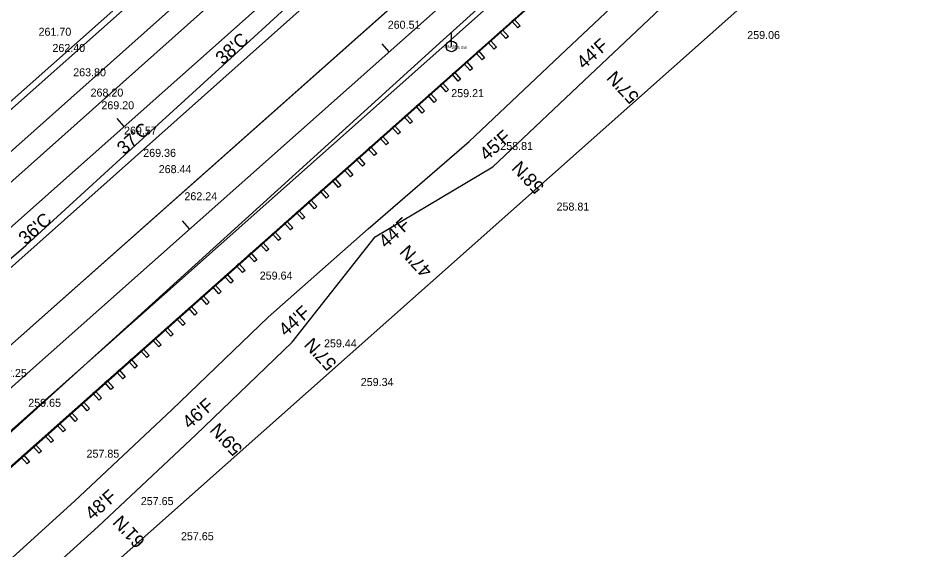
# Model space of a CAD drawing. Extents: x 49683 to 58852, y 49525 to 54803.
# Drawn here: x 54598 to 54939.2, y 52384.9 to 52584.3 of the extents above; entities that cross this region are included whole.
import ezdxf

# ---------------------------------------------------------------- set-up
doc = ezdxf.new("R2010")
doc.units = 0
for name, color, linetype in [('Level 1', 7, 'Continuous'), ('Level 11', 7, 'Continuous'), ('Level 13', 7, 'Continuous'), ('Level 18', 7, 'Continuous'), ('Level 19', 7, 'Continuous'), ('Level 20', 7, 'Continuous'), ('Level 27', 7, 'Continuous'), ('Level 3', 7, 'Continuous'), ('Level 32', 7, 'Continuous'), ('Level 33', 7, 'Continuous'), ('Level 48', 7, 'Continuous'), ('Level 59', 7, 'Continuous'), ('Level 61', 7, 'Continuous'), ('Level 8', 7, 'Continuous'), ('Level 9', 7, 'Continuous')]:
    doc.layers.add(name, color=color, linetype=linetype)

# ---------------------------------------------------------------- blocks, each defined once
blk = doc.blocks.new('GW')
at = {"layer": 'Level 9'}
blk.add_line((0, 0), (0, 5), dxfattribs=at)
blk.add_circle((0, 0), 2, dxfattribs=at)

msp = doc.modelspace()

# ---------------------------------------------------------------- linework, layer by layer
at = {"layer": 'Level 1'}
for p, q in [((52544.81, 50683.3), (55534.58, 53340.86)), ((54637.69, 52543.63), (54635.03, 52546.62))]:
    msp.add_line(p, q, dxfattribs=at)
at = {"layer": 'Level 11'}
for p, q in [((54757.25, 52576.08), (54913.43, 52717.81)), ((54324.2, 52292.62), (54711.21, 52637.72)), ((54450.3, 52297.6), (54757.25, 52576.08))]:
    msp.add_line(p, q, dxfattribs=at)
at = {"layer": 'Level 13'}
for p, q in [((55279.53, 53070), (53969.03, 51905.11)), ((54971.79, 52884.76), (53925.18, 51954.44))]:
    msp.add_line(p, q, dxfattribs=at)
at = {"layer": 'Level 18'}
for p, q in [((54803.29, 52572.34), (54839.6, 52606.76)), ((54674.65, 52566.54), (54711.55, 52600.29)), ((54812.22, 52562.88), (54848.51, 52597.3)), ((54766.92, 52538), (54803.29, 52572.34)), ((54637.73, 52532.81), (54674.65, 52566.54)), ((54775.84, 52528.54), (54812.22, 52562.88)), ((54729.15, 52505.23), (54766.92, 52538)), ((54600.86, 52499.03), (54637.73, 52532.81)), ((54731.79, 52502.23), (54775.84, 52528.54)), ((54691.65, 52472.16), (54729.15, 52505.23)), ((54700.66, 52462.79), (54731.79, 52502.23)), ((54562.88, 52466.5), (54600.86, 52499.03)), ((54655.59, 52437.46), (54691.65, 52472.16)), ((54664.55, 52428.04), (54700.66, 52462.79)), ((54619.13, 52403.22), (54655.59, 52437.46)), ((54627.94, 52393.65), (54664.55, 52428.04)), ((54582.03, 52369.7), (54619.13, 52403.22)), ((54590.74, 52360.05), (54627.94, 52393.65))]:
    msp.add_line(p, q, dxfattribs=at)
at = {"layer": 'Level 19'}
for p, q in [((54181.77, 52078.16), (56150.85, 53828.45)), ((54736.98, 52571.68), (54734.32, 52574.67)), ((54662.24, 52505.24), (54659.58, 52508.23))]:
    msp.add_line(p, q, dxfattribs=at)
at = {"layer": 'Level 20'}
for p, q in [((54173.8, 52087.13), (55269.45, 53061.04)), ((54189.74, 52069.19), (55278.86, 53037.3))]:
    msp.add_line(p, q, dxfattribs=at)
at = {"layer": 'Level 27'}
for p, q in [((54196.38, 52061.72), (54970.77, 52750.06)), ((54196.55, 52061.53), (54970.94, 52749.87)), ((54782.99, 52583.14), (54783.87, 52583.92)), ((54783.87, 52583.92), (54786.13, 52581.38)), ((54785.25, 52580.6), (54782.99, 52583.14)), ((54786.13, 52581.38), (54785.25, 52580.6)), ((54778.5, 52579.15), (54779.39, 52579.94)), ((54780.76, 52576.61), (54778.5, 52579.15)), ((54779.39, 52579.94), (54781.64, 52577.4)), ((54781.64, 52577.4), (54780.76, 52576.61)), ((54774.02, 52575.17), (54774.9, 52575.95)), ((54776.28, 52572.63), (54774.02, 52575.17)), ((54774.9, 52575.95), (54777.16, 52573.41)), ((54769.53, 52571.18), (54770.42, 52571.97)), ((54771.79, 52568.64), (54769.53, 52571.18)), ((54770.42, 52571.97), (54772.68, 52569.42)), ((54777.16, 52573.41), (54776.28, 52572.63)), ((54765.05, 52567.19), (54765.93, 52567.98)), ((54767.31, 52564.65), (54765.05, 52567.19)), ((54765.93, 52567.98), (54768.19, 52565.44)), ((54772.68, 52569.42), (54771.79, 52568.64)), ((54760.56, 52563.21), (54761.45, 52563.99)), ((54761.45, 52563.99), (54763.71, 52561.45)), ((54768.19, 52565.44), (54767.31, 52564.65)), ((54756.08, 52559.22), (54756.96, 52560.01)), ((54756.96, 52560.01), (54759.22, 52557.47)), ((54762.82, 52560.67), (54760.56, 52563.21)), ((54763.71, 52561.45), (54762.82, 52560.67)), ((54758.34, 52556.68), (54756.08, 52559.22)), ((54759.22, 52557.47), (54758.34, 52556.68)), ((54751.6, 52555.24), (54752.48, 52556.02)), ((54753.85, 52552.69), (54751.6, 52555.24)), ((54752.48, 52556.02), (54754.74, 52553.48)), ((54754.74, 52553.48), (54753.85, 52552.69)), ((54747.11, 52551.25), (54747.99, 52552.03)), ((54749.37, 52548.71), (54747.11, 52551.25)), ((54747.99, 52552.03), (54750.25, 52549.49)), ((54742.63, 52547.26), (54743.51, 52548.05)), ((54744.89, 52544.72), (54742.63, 52547.26)), ((54743.51, 52548.05), (54745.77, 52545.51)), ((54750.25, 52549.49), (54749.37, 52548.71)), ((54738.14, 52543.28), (54739.03, 52544.06)), ((54740.4, 52540.74), (54738.14, 52543.28)), ((54739.03, 52544.06), (54741.28, 52541.52)), ((54745.77, 52545.51), (54744.89, 52544.72)), ((54733.66, 52539.29), (54734.54, 52540.08)), ((54734.54, 52540.08), (54736.8, 52537.53)), ((54741.28, 52541.52), (54740.4, 52540.74)), ((54729.17, 52535.3), (54730.06, 52536.09)), ((54730.06, 52536.09), (54732.32, 52533.55)), ((54735.92, 52536.75), (54733.66, 52539.29)), ((54736.8, 52537.53), (54735.92, 52536.75)), ((54731.43, 52532.76), (54729.17, 52535.3)), ((54732.32, 52533.55), (54731.43, 52532.76)), ((54724.69, 52531.32), (54725.57, 52532.1)), ((54726.95, 52528.78), (54724.69, 52531.32)), ((54725.57, 52532.1), (54727.83, 52529.56)), ((54727.83, 52529.56), (54726.95, 52528.78)), ((54720.2, 52527.33), (54721.09, 52528.12)), ((54722.46, 52524.79), (54720.2, 52527.33)), ((54721.09, 52528.12), (54723.35, 52525.58)), ((54715.72, 52523.35), (54716.6, 52524.13)), ((54717.98, 52520.8), (54715.72, 52523.35)), ((54716.6, 52524.13), (54718.86, 52521.59)), ((54723.35, 52525.58), (54722.46, 52524.79)), ((54711.24, 52519.36), (54712.12, 52520.15)), ((54713.49, 52516.82), (54711.24, 52519.36)), ((54712.12, 52520.15), (54714.38, 52517.6)), ((54718.86, 52521.59), (54717.98, 52520.8)), ((54706.75, 52515.37), (54707.63, 52516.16)), ((54707.63, 52516.16), (54709.89, 52513.62)), ((54714.38, 52517.6), (54713.49, 52516.82)), ((54702.27, 52511.39), (54703.15, 52512.17)), ((54703.15, 52512.17), (54705.41, 52509.63)), ((54709.01, 52512.83), (54706.75, 52515.37)), ((54709.89, 52513.62), (54709.01, 52512.83)), ((54704.53, 52508.85), (54702.27, 52511.39)), ((54705.41, 52509.63), (54704.53, 52508.85)), ((54697.78, 52507.4), (54698.67, 52508.19)), ((54700.04, 52504.86), (54697.78, 52507.4)), ((54698.67, 52508.19), (54700.92, 52505.65)), ((54700.92, 52505.65), (54700.04, 52504.86)), ((54693.3, 52503.42), (54694.18, 52504.2)), ((54695.56, 52500.87), (54693.3, 52503.42)), ((54694.18, 52504.2), (54696.44, 52501.66)), ((54688.81, 52499.43), (54689.7, 52500.21)), ((54691.07, 52496.89), (54688.81, 52499.43)), ((54689.7, 52500.21), (54691.96, 52497.67)), ((54696.44, 52501.66), (54695.56, 52500.87)), ((54684.33, 52495.44), (54685.21, 52496.23)), ((54686.59, 52492.9), (54684.33, 52495.44)), ((54685.21, 52496.23), (54687.47, 52493.69)), ((54691.96, 52497.67), (54691.07, 52496.89)), ((54679.84, 52491.46), (54680.73, 52492.24)), ((54680.73, 52492.24), (54682.99, 52489.7)), ((54687.47, 52493.69), (54686.59, 52492.9)), ((54675.36, 52487.47), (54676.24, 52488.26)), ((54676.24, 52488.26), (54678.5, 52485.71)), ((54682.1, 52488.92), (54679.84, 52491.46)), ((54682.99, 52489.7), (54682.1, 52488.92)), ((54677.62, 52484.93), (54675.36, 52487.47)), ((54678.5, 52485.71), (54677.62, 52484.93)), ((54670.88, 52483.48), (54671.76, 52484.27)), ((54673.13, 52480.94), (54670.88, 52483.48)), ((54671.76, 52484.27), (54674.02, 52481.73)), ((54674.02, 52481.73), (54673.13, 52480.94)), ((54666.39, 52479.5), (54667.27, 52480.28)), ((54668.65, 52476.96), (54666.39, 52479.5)), ((54667.27, 52480.28), (54669.53, 52477.74)), ((54661.91, 52475.51), (54662.79, 52476.3)), ((54664.16, 52472.97), (54661.91, 52475.51)), ((54662.79, 52476.3), (54665.05, 52473.76)), ((54669.53, 52477.74), (54668.65, 52476.96)), ((54657.42, 52471.53), (54658.31, 52472.31)), ((54659.68, 52468.98), (54657.42, 52471.53)), ((54658.31, 52472.31), (54660.56, 52469.77)), ((54665.05, 52473.76), (54664.16, 52472.97)), ((54652.94, 52467.54), (54653.82, 52468.33)), ((54653.82, 52468.33), (54656.08, 52465.78)), ((54660.56, 52469.77), (54659.68, 52468.98)), ((54655.2, 52465), (54652.94, 52467.54)), ((54656.08, 52465.78), (54655.2, 52465)), ((54648.45, 52463.55), (54649.34, 52464.34)), ((54650.71, 52461.01), (54648.45, 52463.55)), ((54649.34, 52464.34), (54651.6, 52461.8)), ((54651.6, 52461.8), (54650.71, 52461.01)), ((54643.97, 52459.57), (54644.85, 52460.35)), ((54646.23, 52457.03), (54643.97, 52459.57)), ((54644.85, 52460.35), (54647.11, 52457.81)), ((54647.11, 52457.81), (54646.23, 52457.03)), ((54639.48, 52455.58), (54640.37, 52456.37)), ((54641.74, 52453.04), (54639.48, 52455.58)), ((54640.37, 52456.37), (54642.63, 52453.83)), ((54635, 52451.6), (54635.88, 52452.38)), ((54637.26, 52449.05), (54635, 52451.6)), ((54635.88, 52452.38), (54638.14, 52449.84)), ((54642.63, 52453.83), (54641.74, 52453.04)), ((54630.52, 52447.61), (54631.4, 52448.39)), ((54632.77, 52445.07), (54630.52, 52447.61)), ((54631.4, 52448.39), (54633.66, 52445.85)), ((54638.14, 52449.84), (54637.26, 52449.05)), ((54626.03, 52443.62), (54626.91, 52444.41)), ((54626.91, 52444.41), (54629.17, 52441.87)), ((54633.66, 52445.85), (54632.77, 52445.07)), ((54628.29, 52441.08), (54626.03, 52443.62)), ((54629.17, 52441.87), (54628.29, 52441.08)), ((54621.55, 52439.64), (54622.43, 52440.42)), ((54623.8, 52437.1), (54621.55, 52439.64)), ((54622.43, 52440.42), (54624.69, 52437.88)), ((54624.69, 52437.88), (54623.8, 52437.1)), ((54617.06, 52435.65), (54617.95, 52436.44)), ((54619.32, 52433.11), (54617.06, 52435.65)), ((54617.95, 52436.44), (54620.2, 52433.89)), ((54620.2, 52433.89), (54619.32, 52433.11)), ((54612.58, 52431.66), (54613.46, 52432.45)), ((54614.84, 52429.12), (54612.58, 52431.66)), ((54613.46, 52432.45), (54615.72, 52429.91)), ((54608.09, 52427.68), (54608.98, 52428.46)), ((54610.35, 52425.14), (54608.09, 52427.68)), ((54608.98, 52428.46), (54611.23, 52425.92)), ((54615.72, 52429.91), (54614.84, 52429.12)), ((54603.61, 52423.69), (54604.49, 52424.48)), ((54605.87, 52421.15), (54603.61, 52423.69)), ((54604.49, 52424.48), (54606.75, 52421.94)), ((54611.23, 52425.92), (54610.35, 52425.14)), ((54599.12, 52419.71), (54600.01, 52420.49)), ((54600.01, 52420.49), (54602.27, 52417.95)), ((54606.75, 52421.94), (54605.87, 52421.15)), ((54601.38, 52417.16), (54599.12, 52419.71)), ((54602.27, 52417.95), (54601.38, 52417.16))]:
    msp.add_line(p, q, dxfattribs=at)
at = {"layer": 'Level 3'}
for p, q in [((54524.1, 52459.42), (54718.13, 52632.37)), ((54540.49, 52442.07), (54733.4, 52613.92))]:
    msp.add_line(p, q, dxfattribs=at)
at = {"layer": 'Level 33'}
msp.add_line((54231.59, 52022.1), (55608.96, 53246.42), dxfattribs=at)
at = {"layer": 'Level 8'}
msp.add_line((54015.78, 52039), (54838.64, 52769.14), dxfattribs=at)

# ---------------------------------------------------------------- block references
at = {"layer": 'Level 9'}
msp.add_blockref('GW', (54760.32, 52573.7), dxfattribs=at)

# ---------------------------------------------------------------- texts
at = {"layer": 'Level 32'}
for s, p in [('261.70', (54605.63, 52577.67)), ('260.51', (54736.45, 52580.3)), ('259.06', (54871.14, 52576.44)), ('262.40', (54610.83, 52571.59)), ('263.80', (54618.62, 52562.47)), ('268.20', (54625.12, 52554.86)), ('259.21', (54760.25, 52554.65)), ('269.20', (54629.18, 52550.11)), ('269.57', (54637.66, 52540.61)), ('258.81', (54778.61, 52534.85)), ('269.36', (54644.86, 52532.26)), ('268.44', (54650.65, 52526.16)), ('262.24', (54660.28, 52516)), ('258.81', (54799.7, 52512.12)), ('259.64', (54688.5, 52486.25)), ('259.44', (54712.58, 52460.85)), ('262.25', (54588.98, 52449.75)), ('259.34', (54726.35, 52446.34)), ('259.65', (54601.78, 52438.56)), ('257.85', (54623.61, 52419.48)), ('257.65', (54643.94, 52401.71)), ('257.65', (54658.99, 52388.54))]:
    msp.add_text(s, height=3, dxfattribs=at).set_placement(p)
at = {"layer": 'Level 48'}
for s, rotation, p in [("38'C", 41.6334, (54674.65, 52566.54)), ("44'F", 41.6334, (54809.94, 52564.86)), ("57'N", 132.8528, (54830.97, 52555.04)), ("37'C", 41.6334, (54637.73, 52532.81)), ("45'F", 41.6334, (54773.56, 52530.52)), ("58'N", 132.8528, (54795.42, 52521.26)), ("36'C", 41.6334, (54600.86, 52499.03)), ("44'F", 41.6334, (54735.79, 52497.75)), ("47'N", 132.8528, (54753.42, 52489.8)), ("44'F", 41.6334, (54698.29, 52464.68)), ("57'N", 132.8528, (54717.62, 52455)), ("46'F", 41.6334, (54662.23, 52429.99)), ("59'N", 132.8528, (54682.33, 52423.04)), ("48'F", 41.6334, (54625.78, 52395.74)), ("61'N", 132.8528, (54645.91, 52388.41))]:
    msp.add_text(s, height=5, rotation=rotation, dxfattribs=at).set_placement(p)
at = {"layer": 'Level 59'}
msp.add_text('1385 GW', height=1, dxfattribs=at).set_placement((54760.32, 52572.7))
at = {"layer": 'Level 61'}
msp.add_text('1384 TR', height=1, dxfattribs=at).set_placement((54757.25, 52573.08))

doc.saveas('drawing.dxf')
